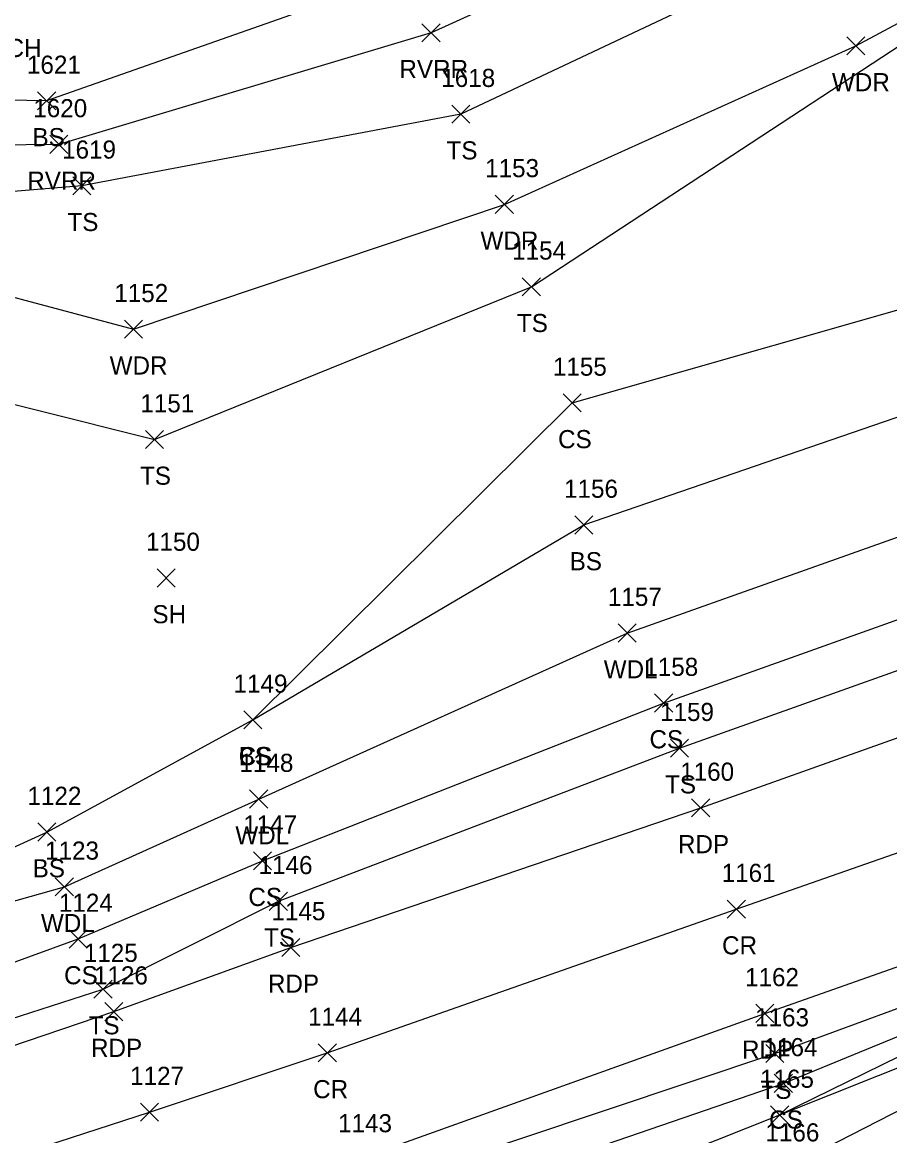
# Model space of a CAD drawing. Extents: x 1443064 to 1445163, y 544063 to 544655.
# Drawn here: x 1443236.3 to 1443332.1, y 544151.7 to 544274.6 of the extents above; entities that cross this region are included whole.
import ezdxf

# ---------------------------------------------------------------- set-up
doc = ezdxf.new("R2010")
doc.units = 0
for name, color, linetype in [('L_A', 7, 'Continuous'), ('L_I', 7, 'Continuous'), ('L_TIC', 7, 'Continuous'), ('LABL', 7, 'Continuous'), ('LAWA', 7, 'Continuous'), ('LAWE', 7, 'Continuous'), ('LELB', 7, 'Continuous'), ('LFNC', 7, 'Continuous'), ('P_A', 7, 'Continuous'), ('P_I', 7, 'Continuous'), ('P_TIC', 7, 'Continuous'), ('PET', 7, 'Continuous'), ('PRC', 7, 'Continuous')]:
    doc.layers.add(name, color=color, linetype=linetype)

msp = doc.modelspace()

# ---------------------------------------------------------------- linework, layer by layer
at = {"layer": 'L_TIC'}
for points in [[(1443280.44, 544272.46), (1443282.44, 544274.46)], [(1443282.44, 544272.46), (1443280.44, 544274.46)], [(1443327.33, 544271.01), (1443329.33, 544273.01)], [(1443329.33, 544271.01), (1443327.33, 544273.01)], [(1443238.01, 544264.94), (1443240.01, 544266.94)], [(1443240.01, 544264.94), (1443238.01, 544266.94)], [(1443283.74, 544263.48), (1443285.74, 544265.48)], [(1443285.74, 544263.48), (1443283.74, 544265.48)], [(1443239.37, 544260.14), (1443241.37, 544262.14)], [(1443241.37, 544260.14), (1443239.37, 544262.14)], [(1443241.9, 544255.57), (1443243.9, 544257.57)], [(1443243.9, 544255.57), (1443241.9, 544257.57)], [(1443288.53, 544253.52), (1443290.53, 544255.52)], [(1443290.53, 544253.52), (1443288.53, 544255.52)], [(1443291.51, 544244.42), (1443293.51, 544246.42)], [(1443293.51, 544244.42), (1443291.51, 544246.42)], [(1443247.61, 544239.73), (1443249.61, 544241.73)], [(1443249.61, 544239.73), (1443247.61, 544241.73)], [(1443296.02, 544231.6), (1443298.02, 544233.6)], [(1443298.02, 544231.6), (1443296.02, 544233.6)], [(1443249.92, 544227.56), (1443251.92, 544229.56)], [(1443251.92, 544227.56), (1443249.92, 544229.56)], [(1443297.3, 544218.12), (1443299.3, 544220.12)], [(1443299.3, 544218.12), (1443297.3, 544220.12)], [(1443251.2, 544212.27), (1443253.2, 544214.27)], [(1443253.2, 544212.27), (1443251.2, 544214.27)], [(1443302.08, 544206.19), (1443304.08, 544208.19)], [(1443304.08, 544206.19), (1443302.08, 544208.19)], [(1443306.11, 544198.46), (1443308.11, 544200.46)], [(1443308.11, 544198.46), (1443306.11, 544200.46)], [(1443260.77, 544196.6), (1443262.77, 544198.6)], [(1443262.77, 544196.6), (1443260.77, 544198.6)], [(1443260.77, 544196.6), (1443262.77, 544198.6)], [(1443262.77, 544196.6), (1443260.77, 544198.6)], [(1443307.86, 544193.48), (1443309.86, 544195.48)], [(1443309.86, 544193.48), (1443307.86, 544195.48)], [(1443261.42, 544187.86), (1443263.42, 544189.86)], [(1443263.42, 544187.86), (1443261.42, 544189.86)], [(1443238.03, 544184.22), (1443240.03, 544186.22)], [(1443240.03, 544184.22), (1443238.03, 544186.22)], [(1443261.84, 544181.05), (1443263.84, 544183.05)], [(1443263.84, 544181.05), (1443261.84, 544183.05)], [(1443239.97, 544178.17), (1443241.97, 544180.17)], [(1443241.97, 544178.17), (1443239.97, 544180.17)], [(1443263.59, 544176.57), (1443265.59, 544178.57)], [(1443265.59, 544176.57), (1443263.59, 544178.57)], [(1443241.5, 544172.41), (1443243.5, 544174.41)], [(1443243.5, 544172.41), (1443241.5, 544174.41)], [(1443244.24, 544166.88), (1443246.24, 544168.88)], [(1443246.24, 544166.88), (1443244.24, 544168.88)], [(1443318.39, 544159.76), (1443320.39, 544161.76)], [(1443320.39, 544159.76), (1443318.39, 544161.76)], [(1443319.32, 544156.47), (1443321.32, 544158.47)], [(1443321.32, 544156.47), (1443319.32, 544158.47)], [(1443318.92, 544152.98), (1443320.92, 544154.98)], [(1443320.92, 544152.98), (1443318.92, 544154.98)], [(1443318.92, 544152.98), (1443320.92, 544154.98)], [(1443320.92, 544152.98), (1443318.92, 544154.98)]]:
    msp.add_lwpolyline(points, dxfattribs=at)
at = {"layer": 'LABL'}
msp.add_lwpolyline([(1443237.46, 544116.95), (1443239.88, 544119.45), (1443238.51, 544123.67), (1443277.41, 544137.07), (1443319.92, 544153.98), (1443347.34, 544164.94), (1443351.22, 544161.82), (1443356.07, 544155.13), (1443361.46, 544147.05)], dxfattribs=at)
at = {"layer": 'LAWA'}
for points in [[(1443161.29, 544157.23), (1443186.09, 544163.69), (1443194.34, 544166.63), (1443196.33, 544167.63), (1443201.36, 544168), (1443240.97, 544179.17), (1443262.42, 544188.86), (1443303.08, 544207.19), (1443347.02, 544222.79), (1443391.79, 544240.14), (1443432.68, 544254.71), (1443466.61, 544275.19), (1443493.21, 544282.75), (1443512.25, 544287.37), (1443549.07, 544304.36), (1443598.9, 544317.54), (1443643.36, 544329.59), (1443677.18, 544341.83), (1443688.03, 544341.71), (1443709.45, 544338.47), (1443741.32, 544354.61), (1443794.32, 544372.46), (1443818.98, 544380.86)], [(1443161.29, 544157.23), (1443145.28, 544154.36), (1443143.53, 544167.56), (1443146.04, 544183.08), (1443157.94, 544207.35), (1443163.64, 544207.35), (1443166.87, 544211.98), (1443169.79, 544215.76), (1443171.76, 544225.15), (1443198.4, 544243.33), (1443223.22, 544247.5), (1443248.61, 544240.73), (1443289.53, 544254.52), (1443328.33, 544272.01), (1443354.38, 544286)]]:
    msp.add_lwpolyline(points, dxfattribs=at)
at = {"layer": 'LAWE'}
msp.add_lwpolyline([(1443627.73, 544516.96), (1443602.93, 544465.06), (1443560.09, 544445.87), (1443514.11, 544419.1), (1443476.33, 544389.4), (1443439.4, 544357.75), (1443402.97, 544339.11), (1443368.14, 544318.06), (1443323.16, 544292.42), (1443281.44, 544273.46), (1443240.37, 544261.14), (1443193.33, 544260.65), (1443164.34, 544237.83), (1443139.78, 544220.74), (1443138.28, 544217.17), (1443133.77, 544210.32), (1443100.97, 544202.05)], dxfattribs=at)
at = {"layer": 'LELB'}
for points in [[(1443623.25, 544521.72), (1443599.67, 544467.52), (1443557.8, 544451.16), (1443512.32, 544424.47), (1443473.97, 544391.39), (1443436.99, 544360.77), (1443402.58, 544340.48), (1443365.21, 544324.82), (1443319.81, 544300.23), (1443279.76, 544280.29), (1443239.01, 544265.94), (1443191.15, 544266.77), (1443161, 544250.15), (1443130.5, 544221.16), (1443098.72, 544215.41)], [(1443630.6, 544513.66), (1443606.19, 544459.79), (1443563.47, 544440.26), (1443516.58, 544414.23), (1443479.57, 544386.27), (1443441.49, 544354.15), (1443406.03, 544333.57), (1443372.48, 544309.35), (1443326.54, 544284.19), (1443284.74, 544264.48), (1443242.9, 544256.57), (1443195.74, 544252.68), (1443182.88, 544237.49), (1443172.34, 544228.16)], [(1443073.59, 544128.34), (1443116.66, 544141.89), (1443162.8, 544149.75), (1443198.07, 544157.24), (1443242.5, 544173.41), (1443262.84, 544182.05), (1443307.11, 544199.46), (1443348.85, 544214.35), (1443394.74, 544233.02), (1443435.02, 544243.93), (1443473.16, 544259.47), (1443514.32, 544272.16), (1443555.56, 544285.54), (1443605.06, 544302.52), (1443644.56, 544313.72), (1443676.09, 544324.26), (1443689.45, 544326.75), (1443708.55, 544330.01), (1443714.07, 544333.45), (1443742.84, 544349.83), (1443793.92, 544368.99), (1443822.61, 544377.56)], [(1443074.67, 544122.4), (1443120.32, 544131.74), (1443165.11, 544143.77), (1443199.58, 544153.13), (1443245.24, 544167.88), (1443264.59, 544177.57), (1443308.86, 544194.48), (1443350.56, 544209.36), (1443397.32, 544225.82), (1443437.1, 544238.98), (1443476.53, 544253.14), (1443516.75, 544265.8), (1443558.95, 544280.95), (1443607.52, 544296.39), (1443646.45, 544306.32), (1443685.12, 544319.06), (1443714.26, 544329.16), (1443721.31, 544331.26), (1443744.28, 544345.57), (1443795.65, 544366.53), (1443822.61, 544377.56)], [(1443082.68, 544086.51), (1443130.13, 544099.67), (1443144.13, 544104.98), (1443172.72, 544113.76), (1443212.83, 544125.42), (1443253.97, 544138.87), (1443319.39, 544160.76), (1443361, 544176.06), (1443409.52, 544193.8), (1443447.54, 544206.03), (1443485.93, 544218.99), (1443527.17, 544233.73), (1443570.65, 544246.93), (1443621.44, 544264.66), (1443656.15, 544276.08), (1443695.78, 544288.38), (1443720.36, 544296.79), (1443749.28, 544306.83), (1443759.63, 544310.57), (1443806.78, 544328.14), (1443835.8, 544338.24)], [(1443319.92, 544153.98), (1443361.38, 544174.3), (1443410.41, 544191.66), (1443447.48, 544203.1), (1443486.62, 544216.08), (1443527.2, 544231.22), (1443571.34, 544244.18), (1443622.82, 544261.27), (1443656.98, 544272.97), (1443695.69, 544285.56), (1443722.38, 544294.2), (1443748.12, 544301.75), (1443761.69, 544309.21), (1443807.82, 544325.32), (1443837.04, 544335.82)], [(1443065.69, 544181.55), (1443109.31, 544188.89), (1443136.73, 544199.63), (1443157.94, 544207.35), (1443161.61, 544194.55), (1443179.72, 544186.99), (1443184.46, 544169.42), (1443186.09, 544163.69), (1443190.43, 544160.91), (1443201.88, 544165.55), (1443201.36, 544168), (1443198.62, 544178.69), (1443186.97, 544194.77), (1443179.33, 544201.28), (1443169.79, 544215.76), (1443186.02, 544215.66), (1443204.39, 544216.66), (1443224.03, 544235.31), (1443250.92, 544228.56), (1443292.51, 544245.42), (1443354.38, 544286)], [(1443261.77, 544197.6), (1443297.02, 544232.6), (1443341.34, 544245.28)], [(1443201.36, 544168), (1443239.03, 544185.22), (1443261.77, 544197.6), (1443298.3, 544219.12), (1443343.36, 544234.64)], [(1443194, 544113.59), (1443212.02, 544119.1), (1443220.44, 544121.4), (1443254.78, 544133.96), (1443275.08, 544141.94), (1443320.32, 544157.47), (1443361.38, 544174.3)]]:
    msp.add_lwpolyline(points, dxfattribs=at)
at = {"layer": 'LFNC'}
msp.add_lwpolyline([(1443239.88, 544119.45), (1443278.62, 544130.94), (1443320.57, 544148.06), (1443338.13, 544157.08), (1443351.22, 544161.82), (1443363.5, 544166.21), (1443412.24, 544182.91), (1443449.91, 544194.79), (1443489.63, 544207.22), (1443534.54, 544218.89), (1443545.24, 544222.13), (1443555.28, 544222.99), (1443566.76, 544221.91), (1443584.49, 544223.6), (1443632.95, 544239.56), (1443668.35, 544248.03), (1443707.08, 544263.81), (1443742.56, 544273.31)], dxfattribs=at)
at = {"layer": 'P_TIC'}
for points in [[(1443310.2, 544186.88), (1443312.2, 544188.88)], [(1443312.2, 544186.88), (1443310.2, 544188.88)], [(1443314.13, 544175.71), (1443316.13, 544177.71)], [(1443316.13, 544175.71), (1443314.13, 544177.71)], [(1443264.96, 544171.48), (1443266.96, 544173.48)], [(1443266.96, 544171.48), (1443264.96, 544173.48)], [(1443245.42, 544164.39), (1443247.42, 544166.39)], [(1443247.42, 544164.39), (1443245.42, 544166.39)], [(1443317.27, 544164.2), (1443319.27, 544166.2)], [(1443319.27, 544164.2), (1443317.27, 544166.2)], [(1443268.99, 544159.83), (1443270.99, 544161.83)], [(1443270.99, 544159.83), (1443268.99, 544161.83)], [(1443249.36, 544153.3), (1443251.36, 544155.3)], [(1443251.36, 544153.3), (1443249.36, 544155.3)]]:
    msp.add_lwpolyline(points, dxfattribs=at)
at = {"layer": 'PET'}
for points in [[(1443075.39, 544117.71), (1443121.41, 544129.24), (1443165.99, 544140.07), (1443200.71, 544149.88), (1443246.42, 544165.39), (1443265.96, 544172.48), (1443311.2, 544187.88), (1443352.92, 544202.76), (1443399.28, 544220.13), (1443438.78, 544233.67), (1443478.75, 544247.35), (1443518.41, 544260.6), (1443561.23, 544274.05), (1443611.7, 544290.5), (1443646.84, 544301.68), (1443684.98, 544314.55), (1443724.57, 544327.54), (1443735.41, 544331.22), (1443748.81, 544336.36), (1443799.43, 544353.96), (1443827.31, 544364.14)], [(1443081.93, 544089.54), (1443128.67, 544104.01), (1443173.03, 544117.15), (1443209.23, 544128.71), (1443253.49, 544142.88), (1443273.3, 544149.07), (1443318.27, 544165.2), (1443359.78, 544179.84), (1443408.54, 544196.96), (1443445.92, 544210.12), (1443484.92, 544223.61), (1443525.67, 544237.02), (1443568.63, 544251.04), (1443620.57, 544267.93), (1443654.52, 544278.93), (1443694.69, 544292.43), (1443717.24, 544299.44), (1443752.8, 544310.97), (1443757.72, 544314.31), (1443805.74, 544330.07), (1443835.35, 544341.18)]]:
    msp.add_lwpolyline(points, dxfattribs=at)
at = {"layer": 'PRC'}
msp.add_lwpolyline([(1443078.47, 544103.68), (1443125.02, 544115.93), (1443169.41, 544128.22), (1443204.47, 544139.4), (1443250.36, 544154.3), (1443269.99, 544160.83), (1443315.13, 544176.71), (1443356.58, 544191.19), (1443403.59, 544208.05), (1443442.67, 544222.02), (1443482.15, 544235.41), (1443522.16, 544248.37), (1443565.47, 544262.64), (1443616.51, 544279.34), (1443650.9, 544289.93), (1443689.58, 544302.53), (1443728.44, 544315.77), (1443753.53, 544324.68), (1443803.56, 544342.2), (1443830.96, 544352.16)], dxfattribs=at)

# ---------------------------------------------------------------- texts
at = {"layer": 'L_A'}
for s, p in [('CH', (1443234.59, 544270.79)), ('RVRR', (1443277.95, 544268.46)), ('WDR', (1443325.69, 544267.01)), ('BS', (1443237.45, 544260.94)), ('TS', (1443283.15, 544259.48)), ('RVRR', (1443236.88, 544256.14)), ('TS', (1443241.31, 544251.57)), ('WDR', (1443286.9, 544249.52)), ('TS', (1443290.92, 544240.42)), ('WDR', (1443245.97, 544235.73)), ('CS', (1443295.46, 544227.6)), ('TS', (1443249.32, 544223.56)), ('BS', (1443296.74, 544214.12)), ('SH', (1443250.69, 544208.27)), ('WDL', (1443300.5, 544202.19)), ('CS', (1443305.55, 544194.46)), ('CS', (1443260.21, 544192.6)), ('BS', (1443260.21, 544192.6)), ('TS', (1443307.27, 544189.48)), ('WDL', (1443259.84, 544183.86)), ('BS', (1443237.47, 544180.22)), ('CS', (1443261.28, 544177.05)), ('WDL', (1443238.38, 544174.17)), ('TS', (1443263, 544172.57)), ('CS', (1443240.94, 544168.41)), ('TS', (1443243.65, 544162.88)), ('TS', (1443317.8, 544155.76)), ('CS', (1443318.76, 544152.47))]:
    msp.add_text(s, height=2, dxfattribs=at).set_placement(p)
at = {"layer": 'L_I'}
for s, p in [('1621', (1443236.84, 544268.94)), ('1618', (1443282.57, 544267.48)), ('1620', (1443237.54, 544264.14)), ('1619', (1443240.72, 544259.57)), ('1153', (1443287.41, 544257.52)), ('1154', (1443290.39, 544248.42)), ('1152', (1443246.48, 544243.73)), ('1155', (1443294.89, 544235.6)), ('1151', (1443249.36, 544231.56)), ('1156', (1443296.12, 544222.12)), ('1150', (1443249.98, 544216.27)), ('1157', (1443300.96, 544210.19)), ('1158', (1443304.98, 544202.46)), ('1149', (1443259.64, 544200.6)), ('1149', (1443259.64, 544200.6)), ('1159', (1443306.72, 544197.48)), ('1148', (1443260.3, 544191.86)), ('1122', (1443236.9, 544188.22)), ('1147', (1443260.71, 544185.05)), ('1123', (1443238.84, 544182.17)), ('1146', (1443262.41, 544180.57)), ('1124', (1443240.37, 544176.41)), ('1125', (1443243.12, 544170.88)), ('1163', (1443317.21, 544163.76)), ('1164', (1443318.14, 544160.47)), ('1165', (1443317.75, 544156.98)), ('1165', (1443317.75, 544156.98)), ('1166', (1443318.35, 544151.06))]:
    msp.add_text(s, height=2, dxfattribs=at).set_placement(p)
at = {"layer": 'P_A'}
for s, p in [('RDP', (1443308.69, 544182.88)), ('CR', (1443313.56, 544171.71)), ('RDP', (1443263.44, 544167.48)), ('RDP', (1443243.91, 544160.39)), ('RDP', (1443315.76, 544160.2)), ('CR', (1443268.43, 544155.83))]:
    msp.add_text(s, height=2, dxfattribs=at).set_placement(p)
at = {"layer": 'P_I'}
for s, p in [('1160', (1443308.94, 544190.88)), ('1161', (1443313.52, 544179.71)), ('1145', (1443263.83, 544175.48)), ('1126', (1443244.24, 544168.39)), ('1162', (1443316.1, 544168.2)), ('1144', (1443267.87, 544163.83)), ('1127', (1443248.23, 544157.3)), ('1143', (1443271.18, 544152.07))]:
    msp.add_text(s, height=2, dxfattribs=at).set_placement(p)

doc.saveas('drawing.dxf')
